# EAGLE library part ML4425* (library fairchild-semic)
Sensorless BLDC Motor Controller Source: http://www.fairchildsemi.com/ds/ML/ML4425.pdf
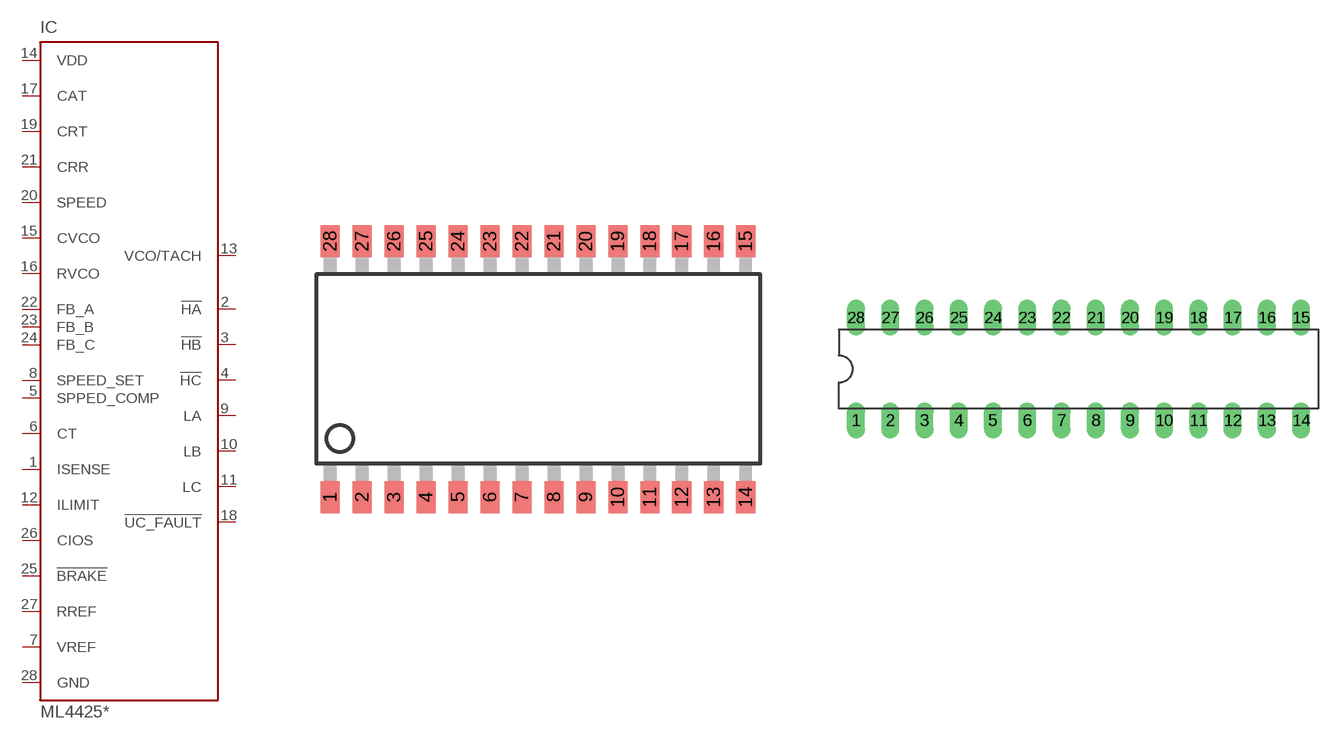
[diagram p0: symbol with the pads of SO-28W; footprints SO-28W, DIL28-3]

Designator prefix IC

## ML4425CS (OC_FARNELL: unknown; OC_NEWARK: unknown), ML4425IS (MF: FAIRCHILD SEMICONDUCTOR; MPN: ML4425ISX; OC_FARNELL: unknown; OC_NEWARK: 82C8713)  [SO-28W]
1  ISENSE  in
2  !HA  pwr
3  !HB  pwr
4  !HC  pwr
5  SPPED_COMP  in
6  CT  in
7  VREF  pwr
8  SPEED_SET  in
9  LA  pwr
10  LB  pwr
11  LC  pwr
12  ILIMIT  in
13  VCO/TACH  pwr
14  VDD  pwr
15  CVCO  pwr
16  RVCO  pwr
17  CAT  pwr
18  !UC_FAULT  pwr
19  CRT  pwr
20  SPEED  pwr
21  CRR  pwr
22  FB_A  in
23  FB_B  in
24  FB_C  in
25  !BRAKE  in
26  CIOS  in
27  RREF  pwr
28  GND  pwr

## ML4425CP (MF: FAIRCHILD SEMICONDUCTOR; MPN: ML4425CP; OC_FARNELL: unknown; OC_NEWARK: 34C1197), ML4425IP (OC_FARNELL: unknown; OC_NEWARK: unknown)  [DIL28-3]
Pads as for SO-28W

## Footprint SO-28W (pad centres in mm)
Small Outline Wide Plastic Gull Wing 300-mil body, package type SO
smd 0.762 x 1.27: 1 -8.255,-5.08; 2 -6.985,-5.08; 3 -5.715,-5.08; 4 -4.445,-5.08; 5 -3.175,-5.08; 6 -1.905,-5.08; 7 -0.635,-5.08; 8 0.635,-5.08; 9 1.905,-5.08; 10 3.175,-5.08; 11 4.445,-5.08; 12 5.715,-5.08; 13 6.985,-5.08; 14 8.255,-5.08; 15 8.255,5.08; 16 6.985,5.08; 17 5.715,5.08; 18 4.445,5.08; 19 3.175,5.08; 20 1.905,5.08; 21 0.635,5.08; 22 -0.635,5.08; 23 -1.905,5.08; 24 -3.175,5.08; 25 -4.445,5.08; 26 -5.715,5.08; 27 -6.985,5.08; 28 -8.255,5.08

## Footprint DIL28-3 (pad centres in mm)
Dual In Line Package Small 28-Pin Narrow PDIP
drill 0.813 long: 1 -16.51,-3.81; 2 -13.97,-3.81; 3 -11.43,-3.81; 4 -8.89,-3.81; 5 -6.35,-3.81; 6 -3.81,-3.81; 7 -1.27,-3.81; 8 1.27,-3.81; 9 3.81,-3.81; 10 6.35,-3.81; 11 8.89,-3.81; 12 11.43,-3.81; 13 13.97,-3.81; 14 16.51,-3.81; 15 16.51,3.81; 16 13.97,3.81; 17 11.43,3.81; 18 8.89,3.81; 19 6.35,3.81; 20 3.81,3.81; 21 1.27,3.81; 22 -1.27,3.81; 23 -3.81,3.81; 24 -6.35,3.81; 25 -8.89,3.81; 26 -11.43,3.81; 27 -13.97,3.81; 28 -16.51,3.81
